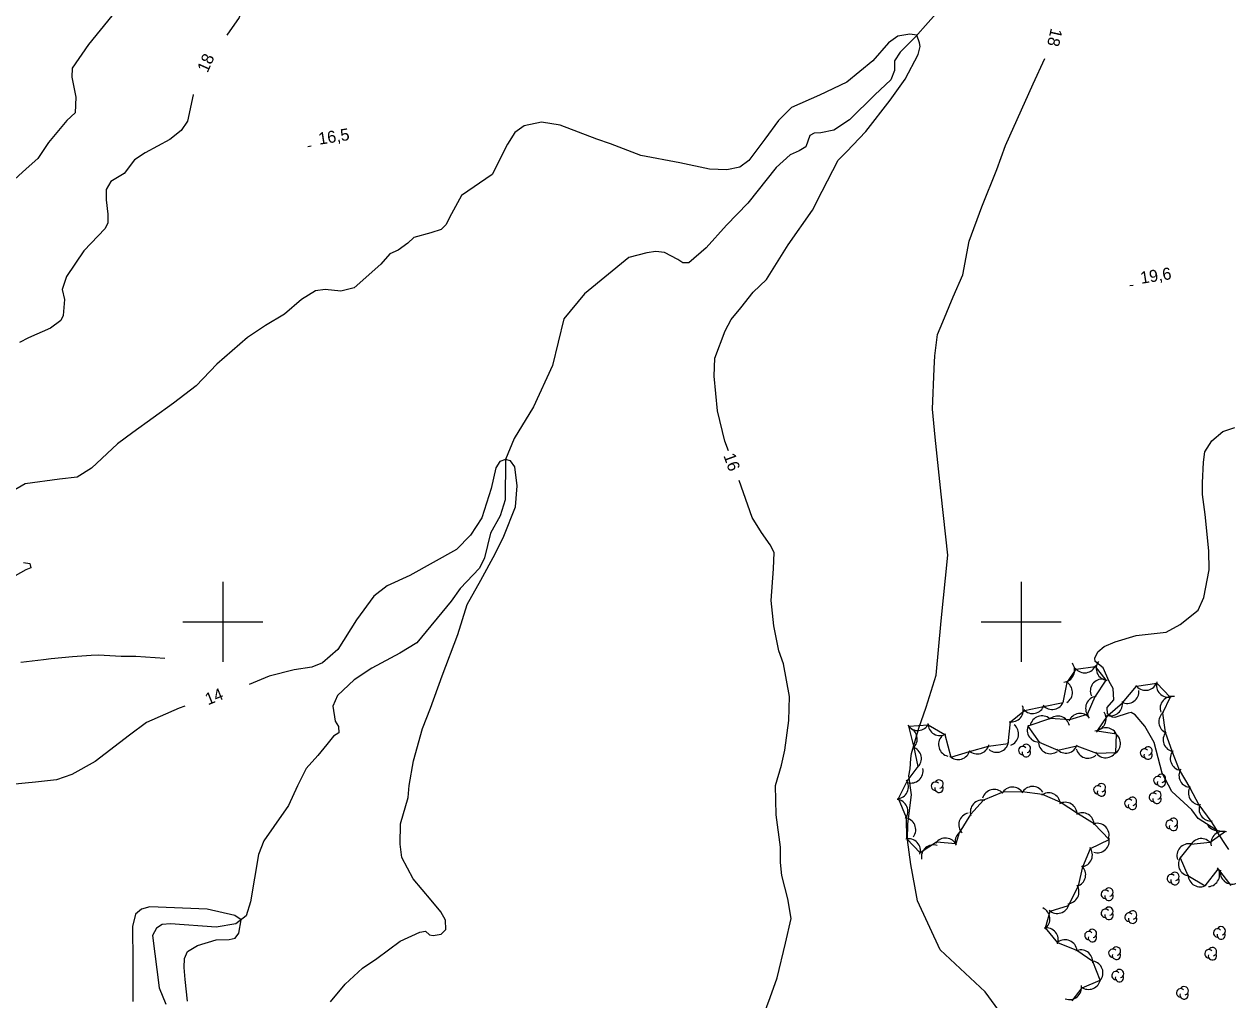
# Model space of a CAD drawing. Extents: x 646142 to 649934, y 5874075 to 5876351.
# Drawn here: x 648150.2 to 648451.8, y 5874505.3 to 5874749.7 of the extents above; entities that cross this region are included whole.
import ezdxf

# ---------------------------------------------------------------- set-up
doc = ezdxf.new("R2010")
doc.units = 0
for name, color, linetype in [('Niveau 1', 7, 'Continuous'), ('Niveau 2', 7, 'Continuous'), ('Niveau 22', 7, 'Continuous'), ('Niveau 3', 7, 'Continuous'), ('Niveau 4', 7, 'Continuous'), ('Niveau 44', 7, 'Continuous'), ('Niveau 61', 7, 'Continuous')]:
    doc.layers.add(name, color=color, linetype=linetype)

msp = doc.modelspace()

# ---------------------------------------------------------------- linework, layer by layer
at = {"layer": 'Niveau 1'}
for points in [[(648172.2, 5874751.77), (648166.34, 5874744.62), (648162.24, 5874738.69), (648162.22, 5874736.46), (648163.18, 5874731.4), (648162.98, 5874727.51), (648160.95, 5874725.55), (648156.34, 5874720.05), (648153.69, 5874716.03), (648150.77, 5874713.51), (648146.91, 5874709.96)], [(648452.01, 5874542.97), (648448.74, 5874547.9), (648444.38, 5874550.73), (648442.77, 5874552.9), (648437.77, 5874557.54), (648435.35, 5874562.08), (648433.33, 5874569.82), (648430.96, 5874573.91), (648428.59, 5874576.7), (648427.59, 5874577.31), (648426.79, 5874577.11), (648423.5, 5874576.08), (648422.8, 5874576.12), (648421.67, 5874576.94), (648421.51, 5874578.56), (648423.2, 5874580.49), (648423.05, 5874583.28), (648422.06, 5874585.05), (648420.56, 5874588.52), (648418.55, 5874590.07), (648418.47, 5874590.88), (648419.25, 5874592.48), (648420.76, 5874593.8), (648423.56, 5874595.01), (648428.79, 5874596.59), (648436.3, 5874597.46), (648439.86, 5874599.34), (648444.31, 5874602.94), (648445.76, 5874606.13), (648447.08, 5874613.04), (648446.98, 5874617.82), (648446.12, 5874626.86), (648445.4, 5874631.93), (648445.47, 5874634.86), (648445.68, 5874640.03), (648446.02, 5874642.63), (648447.74, 5874645.38), (648450.56, 5874647.65), (648453.51, 5874648.65)]]:
    msp.add_lwpolyline(points, dxfattribs=at)
at = {"layer": 'Niveau 2'}
for points in [[(648149.59, 5874848.12), (648154.06, 5874848.1), (648160.43, 5874846.51), (648166.42, 5874844.05), (648179.52, 5874837.36), (648199.1, 5874826.63), (648216.46, 5874817.08), (648232.49, 5874809.05), (648234.5, 5874805.26), (648235.8, 5874796.69), (648233.38, 5874792.68), (648225.57, 5874785.79), (648224.74, 5874782.3), (648222.45, 5874779.25), (648220.41, 5874777.4), (648218.31, 5874773.66), (648217.54, 5874770.65), (648215.26, 5874768.77), (648212.22, 5874767.53), (648207.67, 5874763.66), (648205.84, 5874759.63), (648204.95, 5874754.37), (648204.07, 5874751.35), (648200.98, 5874746.93)], [(648327.34, 5874675.71), (648329.75, 5874678.66), (648332.89, 5874682.61), (648336.22, 5874685.77), (648341.61, 5874694.41), (648347.69, 5874703.13), (648350.17, 5874707.85), (648354.12, 5874715.64), (648356.26, 5874717.74), (648361.06, 5874722.81), (648367.22, 5874730.71), (648370.95, 5874735.91), (648374.23, 5874742.11), (648374.74, 5874744.16), (648374.53, 5874745.08), (648373.87, 5874746.93), (648372.08, 5874747.22), (648369.08, 5874746.68), (648366.77, 5874745.04), (648362.86, 5874740.53), (648356.33, 5874735.17), (648349.49, 5874731.9), (648342.51, 5874728.85), (648339.18, 5874725.58), (648335.76, 5874720.88), (648331.81, 5874715.55), (648329.51, 5874713.91), (648326.29, 5874713.23), (648321.93, 5874713.38), (648314.5, 5874714.99), (648304.7, 5874716.82), (648297.14, 5874719.71), (648293.74, 5874720.89), (648284.48, 5874724.43), (648279.83, 5874725.14), (648275.46, 5874724.23), (648273.15, 5874722.59), (648271.32, 5874719.7), (648267.48, 5874712.02), (648259.78, 5874706.78), (648257.29, 5874702.19)], [(648400.13, 5874494.89), (648390.99, 5874507.3), (648379.69, 5874517.85), (648374.06, 5874530.14), (648373.36, 5874533.81), (648372.37, 5874539.21), (648371.54, 5874545.44), (648371.62, 5874549.43), (648372.57, 5874556.66), (648371.88, 5874561.39), (648372.17, 5874563.17), (648372.39, 5874565.77), (648372.5, 5874567.06), (648374.36, 5874573.34), (648376.19, 5874578.67), (648378.7, 5874586.64), (648379.97, 5874600.23), (648381.67, 5874616.68), (648379.97, 5874631.97), (648378.48, 5874646.23), (648377.8, 5874653.31), (648378.24, 5874663.44), (648378.4, 5874666.62), (648379.06, 5874671.96), (648380.39, 5874675.14), (648382.96, 5874681.38), (648385.36, 5874686.9), (648387, 5874695.39), (648390.17, 5874703.92), (648393.95, 5874713.33), (648396.08, 5874719.29), (648403.03, 5874734.78), (648405.97, 5874741.13)], [(648192.63, 5874732.1), (648192.59, 5874731.99), (648191.13, 5874725.39), (648189.59, 5874723.12), (648186.76, 5874720.84), (648180.52, 5874717.52), (648177.89, 5874715.72), (648175.29, 5874712.3), (648171.97, 5874710.32), (648170.76, 5874708.32), (648170.77, 5874705.74), (648171.24, 5874702.15), (648171.23, 5874699.92), (648170.54, 5874698.56), (648165.22, 5874692.98), (648160.81, 5874686.55), (648159.73, 5874683.27), (648160.33, 5874680.75), (648160.02, 5874676.73), (648159.44, 5874675.5), (648156.81, 5874673.6), (648151.31, 5874671.17), (648149.08, 5874670)], [(648257.29, 5874702.19), (648255.91, 5874699.46), (648254.73, 5874698.29), (648252.11, 5874697.44), (648247.88, 5874696.31), (648246.38, 5874694.86), (648243.97, 5874693.09), (648241.83, 5874692.17), (648239.61, 5874689.6), (648232.92, 5874683.64), (648229.59, 5874682.84), (648225.68, 5874683.27), (648223.25, 5874682.9), (648219.7, 5874680.79), (648215.48, 5874677.07), (648210.71, 5874674.24), (648206.2, 5874671.21), (648198.51, 5874664.56), (648193.3, 5874659.11), (648187.62, 5874654.78), (648177.43, 5874647.41), (648173.6, 5874644.56), (648167.15, 5874638.51), (648163.5, 5874636.27), (648159.1, 5874635.71), (648150.52, 5874634.61), (648145.86, 5874631.91)], [(648326.7, 5874642.83), (648325.81, 5874645.27), (648323.91, 5874652.83), (648323.07, 5874661.55), (648323.23, 5874666.02), (648325.85, 5874672.86), (648327.34, 5874675.71)], [(648250.04, 5874573.29), (648252.01, 5874578.42), (648254.98, 5874586.47), (648258.91, 5874596.85), (648261.23, 5874604.37), (648264.63, 5874610.47), (648268.22, 5874617.05), (648270.37, 5874621.5), (648273.3, 5874628.85), (648273.74, 5874634.06), (648273.16, 5874638.82), (648272.07, 5874640.36), (648270.79, 5874640.67), (648269.43, 5874640.18), (648268.41, 5874638.55), (648267.27, 5874633.38), (648264.92, 5874626.09), (648262.06, 5874621.69), (648258.52, 5874618.16), (648246.83, 5874611.58), (648241.21, 5874609.02), (648237.82, 5874606.44), (648233.46, 5874600.48), (648228.78, 5874593.08), (648224.99, 5874589.76), (648222.28, 5874588.67), (648217.89, 5874587.99), (648211.58, 5874586.42), (648206.62, 5874584.28)], [(648335.18, 5874500.75), (648337.15, 5874505.87), (648338.89, 5874510.84), (648340.99, 5874519.48), (648342.38, 5874525.71), (648341.55, 5874530.66), (648340.05, 5874536.49), (648339.74, 5874539.73), (648339.72, 5874543.6), (648338.59, 5874551.69), (648338.46, 5874559.05), (648339.97, 5874564.13), (648340.78, 5874567.84), (648341.82, 5874575.33), (648341.94, 5874581.32), (648340.45, 5874589.5), (648339.32, 5874592.78), (648338.01, 5874598.98), (648337.4, 5874605.37), (648337.93, 5874613.28), (648338.12, 5874617.41), (648337.11, 5874619.3), (648334.94, 5874622.37), (648332.59, 5874626.12), (648329.35, 5874635.45)], [(648150.11, 5874614.85), (648151.66, 5874614.66), (648151.89, 5874613.51), (648150.64, 5874613.03), (648146.64, 5874610.75)], [(648190.48, 5874578.87), (648189.11, 5874578.41), (648180.89, 5874574.76), (648176.62, 5874571.63), (648167.99, 5874565.01), (648162.21, 5874561.73), (648158.34, 5874560.4), (648153.11, 5874559.87), (648147.06, 5874559.27)], [(648227.01, 5874504.79), (648230.68, 5874509.27), (648234.99, 5874513.22), (648238.62, 5874515.7), (648244.42, 5874520.03), (648249.36, 5874522.29), (648250.75, 5874522.55), (648251.78, 5874521.59), (648252.73, 5874521.45), (648254.7, 5874521.77), (648255.87, 5874522.94), (648255.76, 5874525.28), (648254.62, 5874527.39), (648252.22, 5874530.32), (648247.72, 5874535.62), (648244.85, 5874540.96), (648244.41, 5874544.32), (648244.5, 5874549.37), (648246.44, 5874556.02), (648246.73, 5874558.99), (648247.77, 5874565.2), (648250.04, 5874573.29)], [(648191.13, 5874504.96), (648190.6, 5874510.42), (648190.3, 5874513.45), (648190.43, 5874515.7), (648191.2, 5874517.42), (648193.64, 5874518.96), (648198.32, 5874520.37), (648201.6, 5874520.46), (648203.11, 5874520.73), (648204.04, 5874522), (648204.61, 5874525.4), (648202.99, 5874526.41), (648196.12, 5874528.07), (648181.72, 5874528.62), (648179.66, 5874528.07), (648178.15, 5874526.74), (648177.38, 5874523.72), (648177.44, 5874514.8), (648177.46, 5874504.93)]]:
    msp.add_lwpolyline(points, dxfattribs=at)
at = {"layer": 'Niveau 22'}
msp.add_lwpolyline([(648185.44, 5874590.82), (648178.2, 5874591.29), (648174.58, 5874591.29), (648168.9, 5874591.67), (648167.03, 5874591.54), (648162.32, 5874591.24), (648157.01, 5874590.78), (648155.06, 5874590.45), (648149.37, 5874589.81)], dxfattribs=at)
at = {"layer": 'Niveau 3'}
for p, q in [((648221.34, 5874719.1), (648222.13, 5874719.22)), ((648427.25, 5874684.26), (648428.04, 5874684.38))]:
    msp.add_line(p, q, dxfattribs=at)
at = {"layer": 'Niveau 4'}
for points in [[(648383.2, 5874757.56), (648373.47, 5874746.47), (648369.72, 5874742.68), (648368.28, 5874740.54), (648368.28, 5874738.07), (648367.33, 5874735.74), (648363.34, 5874732.05), (648357.02, 5874725.77), (648353.04, 5874723.13), (648349.82, 5874722.46), (648348.18, 5874722.41), (648347.06, 5874721.83), (648346.04, 5874719.02), (648344.37, 5874718.03), (648342.12, 5874716.98), (648338.67, 5874713.81), (648331.55, 5874704.86), (648326.2, 5874699.38), (648321.11, 5874693.7), (648316.77, 5874689.97), (648315.25, 5874689.93), (648313.99, 5874690.75), (648310.65, 5874692.53), (648308.51, 5874692.78), (648306.19, 5874692.43), (648301.72, 5874691.28), (648290.62, 5874682.16), (648285.47, 5874675.88), (648282.61, 5874664.19), (648277.85, 5874653.84), (648272.98, 5874645.94), (648270.79, 5874640.67), (648270.71, 5874630.55), (648269.46, 5874626.54), (648267.06, 5874622.19), (648265.54, 5874616.04), (648264.27, 5874613.44), (648259.47, 5874608.38), (648257.19, 5874605.21), (648248.58, 5874594.71), (648244.36, 5874592.17), (648237.33, 5874588.41), (648232.91, 5874585.5), (648228.71, 5874581.55), (648227.57, 5874578.85), (648228.16, 5874575.15), (648229, 5874573.82), (648229.04, 5874572.18), (648227.71, 5874571.34), (648226.03, 5874569.29), (648223.83, 5874566.49), (648220.86, 5874563.25), (648218.7, 5874558.92), (648216.47, 5874554), (648212.76, 5874548.7), (648210.29, 5874545.16), (648208.98, 5874541.74), (648206.96, 5874529.9), (648205.89, 5874526.39), (648203.27, 5874524.36), (648198.3, 5874523.51), (648186.93, 5874524.37)], [(648186.93, 5874524.37), (648184.83, 5874524.15), (648183.39, 5874523.3), (648182.39, 5874521.44), (648184.03, 5874508.33), (648185.72, 5874504.27)]]:
    msp.add_lwpolyline(points, dxfattribs=at)
at = {"layer": 'Niveau 44'}
for points in [[(648412.75, 5874505.11), (648415.32, 5874508.36), (648419.8, 5874510.23), (648417.95, 5874514.9), (648413.96, 5874517.67), (648409.2, 5874519.61), (648406.1, 5874523.34), (648407.25, 5874527.56), (648411.89, 5874528.99), (648414.35, 5874533.9), (648415.43, 5874538.64), (648417.39, 5874543.2), (648422.07, 5874545.51), (648418.27, 5874549.43), (648414.13, 5874551.96), (648409.79, 5874554.83), (648405.33, 5874556.73), (648400.23, 5874557.45), (648395.38, 5874557.3), (648390.61, 5874555.34), (648387.32, 5874551.77), (648384.46, 5874547.16), (648383.63, 5874544.37), (648378.8, 5874544.84), (648374.73, 5874542.12), (648371.38, 5874545.64), (648371.26, 5874550.89), (648369.28, 5874555.74), (648371.42, 5874560.09), (648374.24, 5874563.76), (648373.23, 5874568.51), (648371.83, 5874573.84), (648376.67, 5874574.18), (648380.88, 5874571.79), (648382.39, 5874566.14), (648387.05, 5874567.49), (648391.85, 5874568.88), (648396.74, 5874569.52), (648397.32, 5874574.95), (648400.86, 5874577.8), (648405.61, 5874578.8), (648410.51, 5874579.79), (648411.53, 5874584.82), (648413.78, 5874588.13), (648418.58, 5874588.85), (648421.2, 5874585.4), (648418.45, 5874581.26), (648416.58, 5874576.78), (648412.11, 5874575.46), (648407.36, 5874575.79), (648401.68, 5874573.84), (648404.48, 5874569.88)], [(648404.48, 5874569.88), (648409.2, 5874567.86), (648413.94, 5874568.91), (648418.84, 5874567.09), (648423.68, 5874567.31), (648423.85, 5874571.88), (648419.05, 5874572.58), (648421.69, 5874576.58), (648425.4, 5874579.71), (648428.91, 5874583.86), (648433.96, 5874584.65), (648437.31, 5874581.13), (648435.41, 5874577.14), (648436.06, 5874572.33), (648437.84, 5874567.44), (648439.56, 5874562.9), (648442.22, 5874558.43), (648444.55, 5874554.18), (648447.52, 5874550.11), (648449.01, 5874547.75), (648451.18, 5874547.46), (648447.38, 5874544.71), (648442.55, 5874544.22), (648439.8, 5874540.89), (648441.72, 5874536.43), (648446.08, 5874533.91), (648449.38, 5874538.09), (648452.54, 5874533.98)]]:
    msp.add_lwpolyline(points, dxfattribs=at)
for centre, radius, start, end in [((648410.4, 5874587.89), 3, 275.0837, 35.0617), ((648415.92, 5874590.24), 3, 218.5521, 338.5301), ((648421.8, 5874588.34), 3, 144.4939, 264.4719), ((648409.86, 5874582.32), 3, 302.3062, 62.2841), ((648420.33, 5874582.68), 3, 83.9622, 203.9401), ((648431.15, 5874585.85), 3, 215.761, 335.739), ((648436.91, 5874584.1), 3, 163.574, 283.5519), ((648419.14, 5874578.34), 3, 97.3576, 217.3355), ((648426.51, 5874582.58), 3, 244.9333, 4.9112), ((648437.81, 5874578.33), 3, 78.9776, 198.9556), ((648397.54, 5874577.94), 3, 259.7505, 19.7284), ((648402.87, 5874580.03), 3, 221.8712, 341.8491), ((648407.79, 5874581.06), 3, 220.9513, 340.9292), ((648422.41, 5874579.49), 3, 250.169, 10.1469), ((648405.23, 5874573.47), 3, 49.1338, 169.1117), ((648409.17, 5874573.4), 3, 12.9778, 132.9557), ((648414.77, 5874574.06), 3, 38.2491, 158.227), ((648418.28, 5874575.73), 3, 273.7895, 33.7675), ((648437.48, 5874574.97), 3, 127.7206, 247.6986), ((648374.12, 5874575.77), 3, 214.0768, 334.0548), ((648370.96, 5874570.65), 3, 312.3031, 72.2811), ((648379.64, 5874574.52), 3, 180.3752, 300.3531), ((648396.36, 5874571.93), 3, 290.2512, 50.2292), ((648404.52, 5874572.88), 3, 155.313, 275.291), ((648421.2, 5874570.49), 3, 21.7148, 141.6928), ((648421.89, 5874569.56), 3, 302.6309, 62.6088), ((648438.58, 5874570.47), 3, 140.6854, 260.6634), ((648382.31, 5874569.29), 3, 136.8281, 256.8061), ((648389.03, 5874569.9), 3, 226.2069, 346.1849), ((648393.85, 5874570.32), 3, 230.6684, 350.6463), ((648401.3, 5874568.28), 1.05, 282.2692, 149.7263), ((648407.33, 5874569.98), 3, 186.4591, 306.437), ((648411.19, 5874570.11), 3, 222.4641, 342.442), ((648372.01, 5874565.77), 3, 311.9726, 71.9506), ((648384.22, 5874568.51), 3, 226.2069, 346.1849), ((648400.4, 5874567.75), 1.05, 44.1154, 269.804), ((648401.3, 5874567.23), 1.05, 166.9369, 29.6212), ((648416.75, 5874568.84), 3, 191.6234, 311.6013), ((648421.18, 5874568.96), 3, 212.5821, 332.5601), ((648430.9, 5874567.13), 1.05, 44.1154, 269.804), ((648431.8, 5874566.61), 1.05, 166.9369, 29.6212), ((648431.8, 5874567.66), 1.05, 282.2692, 149.7263), ((648440.35, 5874565.79), 3, 140.6854, 260.6634), ((648372.43, 5874562.63), 3, 252.5258, 12.5037), ((648442.53, 5874561.54), 3, 148.7267, 268.7046), ((648368.76, 5874558.69), 3, 273.8062, 33.7841), ((648379.43, 5874559.36), 1.05, 282.2692, 149.7263), ((648434.24, 5874560.26), 1.05, 44.1154, 269.804), ((648435.14, 5874559.74), 1.05, 166.9369, 29.6212), ((648435.14, 5874560.79), 1.05, 282.2692, 149.7263), ((648378.53, 5874558.83), 1.05, 44.1154, 269.804), ((648379.43, 5874558.31), 1.05, 166.9369, 29.6212), ((648393.23, 5874555.03), 3, 43.6052, 163.5832), ((648397.86, 5874555.61), 3, 31.7341, 151.712), ((648402.86, 5874555.76), 3, 31.7341, 151.712), ((648406.87, 5874554.16), 3, 7.0072, 126.9852), ((648419.21, 5874557.92), 1.05, 44.1154, 269.804), ((648420.11, 5874557.4), 1.05, 166.9369, 29.6212), ((648420.11, 5874558.45), 1.05, 282.2692, 149.7263), ((648433.12, 5874556.07), 1.05, 44.1154, 269.804), ((648434.02, 5874556.6), 1.05, 282.2692, 149.7263), ((648444.93, 5874557.15), 3, 148.7267, 268.7046), ((648368.62, 5874552.55), 3, 323.2433, 83.2212), ((648390.26, 5874552.36), 3, 77.2625, 197.2405), ((648411.02, 5874551.8), 3, 358.596, 118.5739), ((648426.98, 5874554.52), 1.05, 44.1154, 269.804), ((648427.88, 5874554), 1.05, 166.9369, 29.6212), ((648427.88, 5874555.05), 1.05, 282.2692, 149.7263), ((648434.02, 5874555.55), 1.05, 166.9369, 29.6212), ((648447.56, 5874553.11), 3, 155.1607, 275.1387), ((648387.38, 5874549.17), 3, 103.1467, 223.1246), ((648415.28, 5874549.19), 3, 358.596, 118.5739), ((648370.6, 5874547.96), 3, 323.2433, 83.2212), ((648419.03, 5874546.55), 3, 343.9782, 103.9561), ((648437.26, 5874549.27), 1.05, 44.1154, 269.804), ((648438.16, 5874548.75), 1.05, 166.9369, 29.6212), ((648438.16, 5874549.8), 1.05, 282.2692, 149.7263), ((648449.21, 5874550.74), 3, 206.3347, 272.0852), ((648371.78, 5874542.67), 3, 343.4979, 103.4759), ((648381.05, 5874542.85), 3, 24.4492, 144.4272), ((648386.45, 5874544.91), 3, 125.5025, 185.4094), ((648419.09, 5874545.16), 3, 252.5344, 12.5123), ((648445.14, 5874542.71), 3, 35.7616, 155.7395), ((648450.55, 5874544.53), 3, 71.8933, 191.8713), ((648378.01, 5874541.13), 3, 70.7927, 190.7706), ((648414.85, 5874541.61), 3, 278.1199, 38.0978), ((648442.03, 5874541.42), 3, 79.0783, 199.0563), ((648442.38, 5874539.36), 3, 143.3382, 263.3161), ((648413.17, 5874536.66), 3, 287.0664, 47.0443), ((648437.62, 5874535.71), 1.05, 44.1154, 269.804), ((648438.52, 5874536.24), 1.05, 282.2692, 149.7263), ((648444.83, 5874536.63), 3, 180.6959, 300.6739), ((648446.73, 5874536.68), 3, 273.9437, 33.9216), ((648452.86, 5874537.32), 3, 170.6374, 290.6153), ((648411.49, 5874532.37), 3, 273.4197, 33.3977), ((648422, 5874532.29), 1.05, 282.2692, 149.7263), ((648438.52, 5874535.19), 1.05, 166.9369, 29.6212), ((648421.1, 5874531.76), 1.05, 44.1154, 269.804), ((648422, 5874531.24), 1.05, 166.9369, 29.6212), ((648404.2, 5874525.61), 3, 305.4923, 65.4702), ((648409.06, 5874529.96), 3, 227.0519, 347.0298), ((648421.09, 5874526.99), 1.05, 44.1154, 269.804), ((648421.99, 5874526.47), 1.05, 166.9369, 29.6212), ((648421.99, 5874527.52), 1.05, 282.2692, 149.7263), ((648427.03, 5874526.04), 1.05, 44.1154, 269.804), ((648427.93, 5874526.57), 1.05, 282.2692, 149.7263), ((648427.93, 5874525.52), 1.05, 166.9369, 29.6212), ((648406.3, 5874520.35), 3, 339.7606, 99.7386), ((648416.96, 5874521.41), 1.05, 44.1154, 269.804), ((648417.86, 5874520.89), 1.05, 166.9369, 29.6212), ((648417.86, 5874521.94), 1.05, 282.2692, 149.7263), ((648449.21, 5874522.07), 1.05, 44.1154, 269.804), ((648450.11, 5874521.55), 1.05, 166.9369, 29.6212), ((648450.11, 5874522.6), 1.05, 282.2692, 149.7263), ((648411, 5874517.36), 3, 6.5226, 126.5006), ((648414.95, 5874514.84), 3, 355.2741, 115.252), ((648422.97, 5874517), 1.05, 44.1154, 269.804), ((648423.87, 5874517.53), 1.05, 282.2692, 149.7263), ((648447.03, 5874516.86), 1.05, 44.1154, 269.804), ((648447.93, 5874517.39), 1.05, 282.2692, 149.7263), ((648417.49, 5874512.09), 3, 319.5916, 79.5695), ((648423.87, 5874516.48), 1.05, 166.9369, 29.6212), ((648447.93, 5874516.34), 1.05, 166.9369, 29.6212), ((648423.74, 5874511.38), 1.05, 44.1154, 269.804), ((648424.64, 5874511.91), 1.05, 282.2692, 149.7263), ((648412.12, 5874508.4), 3, 249.3407, 9.3186), ((648416.88, 5874510.93), 3, 232.6498, 352.6277), ((648424.64, 5874510.86), 1.05, 166.9369, 29.6212), ((648439.94, 5874507.08), 1.05, 44.1154, 269.804), ((648440.84, 5874506.56), 1.05, 166.9369, 29.6212), ((648440.84, 5874507.61), 1.05, 282.2692, 149.7263)]:
    msp.add_arc(centre, radius, start, end, dxfattribs=at)
at = {"layer": 'Niveau 61'}
for points in [[(648200, 5874610), (648200, 5874600), (648200, 5874590)], [(648400, 5874610), (648400, 5874600), (648400, 5874590)], [(648190, 5874600), (648200, 5874600), (648210, 5874600)], [(648390, 5874600), (648400, 5874600), (648410, 5874600)]]:
    msp.add_lwpolyline(points, dxfattribs=at)

# ---------------------------------------------------------------- texts
at = {"layer": 'Niveau 2'}
for s, rotation, p in [('18', 257.1989, (648407.47, 5874748.87)), ('18', 66.0011, (648196.18, 5874737.39)), ('16', 289.8324, (648325.37, 5874641.65)), ('14', 22.1133, (648196.29, 5874579.08))]:
    msp.add_text(s, height=3, rotation=rotation, dxfattribs=at).set_placement(p)
at = {"layer": 'Niveau 3'}
for s, p in [('16,5 ', (648224.19, 5874719.51)), ('19,6 ', (648430.1, 5874684.67))]:
    msp.add_text(s, height=3, rotation=8.9405, dxfattribs=at).set_placement(p)

doc.saveas('drawing.dxf')
